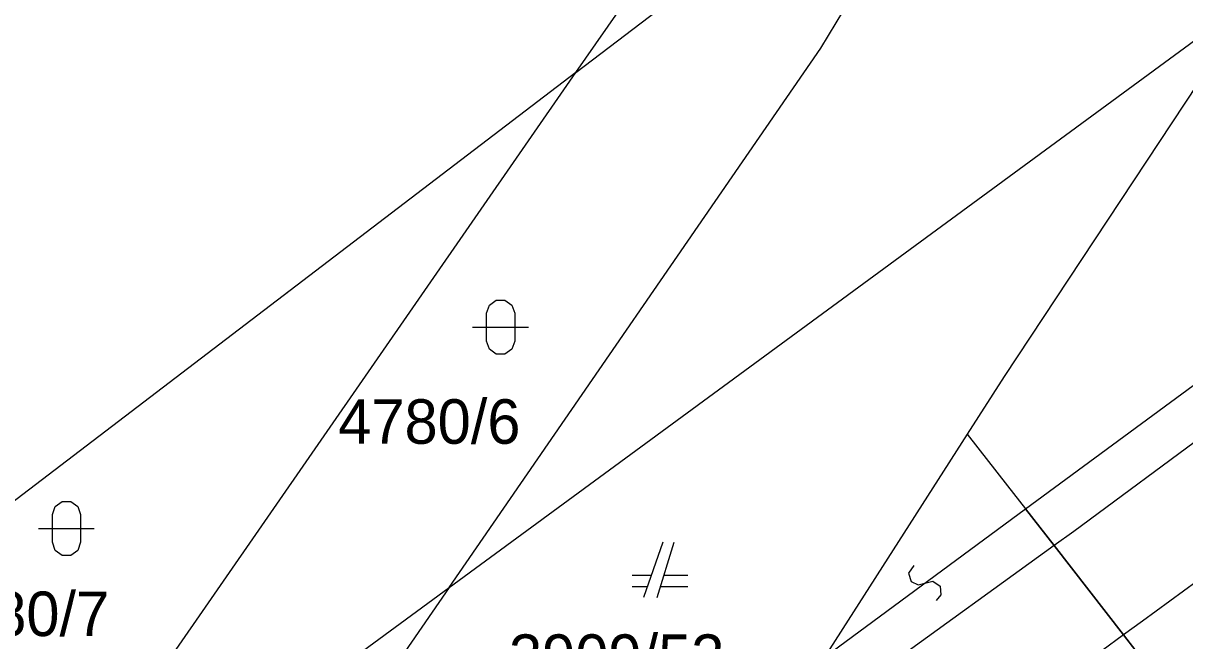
# Model space of a CAD drawing. Extents: x -266179 to -264727, y -1243225 to -1241702.
# Drawn here: x -265417.61 to -265375.91, y -1242967.89 to -1242945.7 of the extents above; entities that cross this region are included whole.
import ezdxf

# ---------------------------------------------------------------- set-up
doc = ezdxf.new("R2010")
doc.units = 0
doc.layers.add('Vrstva 1', color=7, linetype='Continuous')
doc.layers.add('Vrstva 2', color=7, linetype='Continuous')

msp = doc.modelspace()

# ---------------------------------------------------------------- linework, layer by layer
at = {"layer": 'Vrstva 1'}
for p, q in [((-265388.98, -1242946.59), (-265382.64, -1242936.11)), ((-265397.77, -1242947.47), (-265390.99, -1242937.67)), ((-265397.77, -1242947.47), (-265386.97, -1242939.22)), ((-265402.32, -1242965.97), (-265373.36, -1242944.7)), ((-265373.36, -1242944.7), (-265382.4, -1242958.39)), ((-265402.32, -1242965.97), (-265388.98, -1242946.59)), ((-265397.77, -1242947.47), (-265424.35, -1242967.76)), ((-265416.44, -1242974.44), (-265397.77, -1242947.47)), ((-265381.63, -1242963.15), (-265365.72, -1242951.43)), ((-265382.4, -1242958.39), (-265383.72, -1242960.46)), ((-265383.72, -1242960.46), (-265388.85, -1242968.48)), ((-265383.72, -1242960.46), (-265382.28, -1242962.32)), ((-265382.28, -1242962.32), (-265381.63, -1242963.15)), ((-265380.6, -1242964.47), (-265381.63, -1242963.15)), ((-265381.63, -1242963.15), (-265380.6, -1242964.47)), ((-265394.65, -1242964.34), (-265395.35, -1242966.34)), ((-265394.85, -1242966.34), (-265394.25, -1242964.34)), ((-265378.11, -1242967.68), (-265380.6, -1242964.47)), ((-265380.6, -1242964.47), (-265378.11, -1242967.68)), ((-265395.07, -1242965.54), (-265395.75, -1242965.54)), ((-265393.75, -1242965.54), (-265394.61, -1242965.54)), ((-265402.32, -1242965.97), (-265410.97, -1242978.54)), ((-265408.54, -1242970.54), (-265402.32, -1242965.97)), ((-265395.75, -1242965.94), (-265395.21, -1242965.94)), ((-265394.73, -1242965.94), (-265393.75, -1242965.94)), ((-265376.38, -1242969.9), (-265378.11, -1242967.68)), ((-265378.11, -1242967.68), (-265376.38, -1242969.9))]:
    msp.add_line(p, q, dxfattribs=at)
for points in [[(-265400.98, -1242956.12), (-265400.88, -1242955.83), (-265400.63, -1242955.65), (-265400.32, -1242955.65), (-265400.07, -1242955.83), (-265399.97, -1242956.12), (-265399.97, -1242957.12), (-265400.07, -1242957.41), (-265400.32, -1242957.59), (-265400.63, -1242957.59), (-265400.88, -1242957.41), (-265400.98, -1242957.12)], [(-265416.57, -1242963.35), (-265416.47, -1242963.06), (-265416.22, -1242962.88), (-265415.91, -1242962.88), (-265415.66, -1242963.06), (-265415.56, -1242963.35), (-265415.56, -1242964.35), (-265415.66, -1242964.64), (-265415.91, -1242964.82), (-265416.22, -1242964.82), (-265416.47, -1242964.64), (-265416.57, -1242964.35)]]:
    msp.add_lwpolyline(points, close=True, dxfattribs=at)
for points in [[(-265401.48, -1242956.62), (-265400.21, -1242956.62), (-265399.48, -1242956.62)], [(-265417.07, -1242963.85), (-265415.8, -1242963.85), (-265415.07, -1242963.85)]]:
    msp.add_lwpolyline(points, dxfattribs=at)
at = {"layer": 'Vrstva 2'}
for p, q in [((-265363.78, -1242952.02), (-265379.9, -1242963.96)), ((-265361.33, -1242955.3), (-265377.43, -1242967.19)), ((-265388.85, -1242968.48), (-265381.63, -1242963.15)), ((-265379.9, -1242963.96), (-265380.6, -1242964.47)), ((-265380.6, -1242964.47), (-265391.17, -1242972.11)), ((-265377.43, -1242967.19), (-265378.11, -1242967.68)), ((-265378.11, -1242967.68), (-265393.74, -1242979.08))]:
    msp.add_line(p, q, dxfattribs=at)
msp.add_lwpolyline([(-265385.645, -1242965.182), (-265385.829, -1242965.455), (-265385.74, -1242965.761), (-265385.478, -1242965.879), (-265384.957, -1242965.743), (-265384.699, -1242965.925), (-265384.667, -1242966.237), (-265384.835, -1242966.448)], dxfattribs=at)

# ---------------------------------------------------------------- texts
at = {"layer": 'Vrstva 1'}
for s, p in [('4780/6', (-265406.306, -1242960.81)), ('4780/7', (-265421.072, -1242967.72)), ('3909/53', (-265400.173, -1242969.26))]:
    msp.add_text(s, height=1.6, dxfattribs=at).set_placement(p)

doc.saveas('drawing.dxf')
